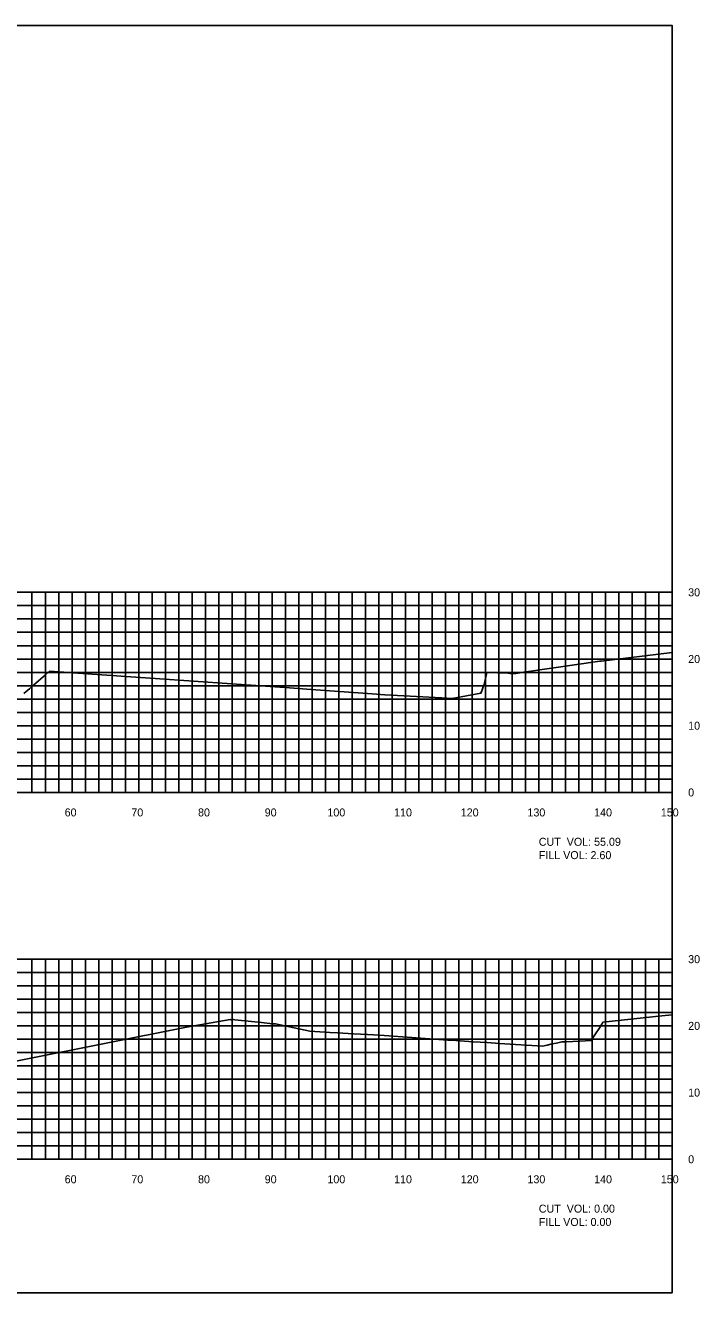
# Model space of a CAD drawing. Extents: x 1800624 to 1802445, y 250079 to 250269.
# Drawn here: x 1802344 to 1802445.1, y 250079.4 to 250269.4 of the extents above; entities that cross this region are included whole.
import ezdxf

# ---------------------------------------------------------------- set-up
doc = ezdxf.new("R2010")
doc.units = 0
for name, color, linetype in [('10', 7, 'Continuous'), ('31', 7, 'Continuous'), ('60', 7, 'Continuous'), ('ANNO-TXT', 7, 'Continuous'), ('Level 62', 7, 'Continuous'), ('M-ROADS', 7, 'Continuous')]:
    doc.layers.add(name, color=color, linetype=linetype)

msp = doc.modelspace()

# ---------------------------------------------------------------- linework, layer by layer
msp.add_lwpolyline([(1802141, 250079.43), (1802441, 250079.43), (1802441, 250269.43), (1802141, 250269.43)], close=True)
at = {"layer": '60'}
for p, q in [((1802441, 250154.43), (1802441, 250184.43)), ((1802441.06, 250184.43), (1802441, 250184.43)), ((1802441.06, 250174.43), (1802441, 250174.43)), ((1802441.06, 250164.43), (1802441, 250164.43)), ((1802141, 250154.43), (1802441, 250154.43)), ((1802351, 250154.37), (1802351, 250154.43)), ((1802361, 250154.37), (1802361, 250154.43)), ((1802371, 250154.37), (1802371, 250154.43)), ((1802381, 250154.37), (1802381, 250154.43)), ((1802391, 250154.37), (1802391, 250154.43)), ((1802401, 250154.37), (1802401, 250154.43)), ((1802411, 250154.37), (1802411, 250154.43)), ((1802421, 250154.37), (1802421, 250154.43)), ((1802431, 250154.37), (1802431, 250154.43)), ((1802441, 250154.37), (1802441, 250154.43)), ((1802441.06, 250154.43), (1802441, 250154.43)), ((1802441, 250099.43), (1802441, 250129.43)), ((1802441.06, 250129.43), (1802441, 250129.43)), ((1802441.06, 250119.43), (1802441, 250119.43)), ((1802441.06, 250109.43), (1802441, 250109.43)), ((1802141, 250099.43), (1802441, 250099.43)), ((1802351, 250099.37), (1802351, 250099.43)), ((1802361, 250099.37), (1802361, 250099.43)), ((1802371, 250099.37), (1802371, 250099.43)), ((1802381, 250099.37), (1802381, 250099.43)), ((1802391, 250099.37), (1802391, 250099.43)), ((1802401, 250099.37), (1802401, 250099.43)), ((1802411, 250099.37), (1802411, 250099.43)), ((1802421, 250099.37), (1802421, 250099.43)), ((1802431, 250099.37), (1802431, 250099.43)), ((1802441, 250099.37), (1802441, 250099.43)), ((1802441.06, 250099.43), (1802441, 250099.43))]:
    msp.add_line(p, q, dxfattribs=at)
at = {"layer": 'Level 62'}
for p, q in [((1802141, 250184.43), (1802441, 250184.43)), ((1802345, 250154.43), (1802345, 250184.43)), ((1802347, 250154.43), (1802347, 250184.43)), ((1802349, 250154.43), (1802349, 250184.43)), ((1802351, 250154.43), (1802351, 250184.43)), ((1802353, 250154.43), (1802353, 250184.43)), ((1802355, 250154.43), (1802355, 250184.43)), ((1802357, 250154.43), (1802357, 250184.43)), ((1802359, 250154.43), (1802359, 250184.43)), ((1802361, 250154.43), (1802361, 250184.43)), ((1802363, 250154.43), (1802363, 250184.43)), ((1802365, 250154.43), (1802365, 250184.43)), ((1802367, 250154.43), (1802367, 250184.43)), ((1802369, 250154.43), (1802369, 250184.43)), ((1802371, 250154.43), (1802371, 250184.43)), ((1802373, 250154.43), (1802373, 250184.43)), ((1802375, 250154.43), (1802375, 250184.43)), ((1802377, 250154.43), (1802377, 250184.43)), ((1802379, 250154.43), (1802379, 250184.43)), ((1802381, 250154.43), (1802381, 250184.43)), ((1802383, 250154.43), (1802383, 250184.43)), ((1802385, 250154.43), (1802385, 250184.43)), ((1802387, 250154.43), (1802387, 250184.43)), ((1802389, 250154.43), (1802389, 250184.43)), ((1802391, 250154.43), (1802391, 250184.43)), ((1802393, 250154.43), (1802393, 250184.43)), ((1802395, 250154.43), (1802395, 250184.43)), ((1802397, 250154.43), (1802397, 250184.43)), ((1802399, 250154.43), (1802399, 250184.43)), ((1802401, 250154.43), (1802401, 250184.43)), ((1802403, 250154.43), (1802403, 250184.43)), ((1802405, 250154.43), (1802405, 250184.43)), ((1802407, 250154.43), (1802407, 250184.43)), ((1802409, 250154.43), (1802409, 250184.43)), ((1802411, 250154.43), (1802411, 250184.43)), ((1802413, 250154.43), (1802413, 250184.43)), ((1802415, 250154.43), (1802415, 250184.43)), ((1802417, 250154.43), (1802417, 250184.43)), ((1802419, 250154.43), (1802419, 250184.43)), ((1802421, 250154.43), (1802421, 250184.43)), ((1802423, 250154.43), (1802423, 250184.43)), ((1802425, 250154.43), (1802425, 250184.43)), ((1802427, 250154.43), (1802427, 250184.43)), ((1802429, 250154.43), (1802429, 250184.43)), ((1802431, 250154.43), (1802431, 250184.43)), ((1802433, 250154.43), (1802433, 250184.43)), ((1802435, 250154.43), (1802435, 250184.43)), ((1802437, 250154.43), (1802437, 250184.43)), ((1802439, 250154.43), (1802439, 250184.43)), ((1802441, 250154.43), (1802441, 250184.43)), ((1802141, 250182.43), (1802441, 250182.43)), ((1802141, 250180.43), (1802441, 250180.43)), ((1802141, 250178.43), (1802441, 250178.43)), ((1802141, 250176.43), (1802441, 250176.43)), ((1802141, 250174.43), (1802441, 250174.43)), ((1802141, 250172.43), (1802441, 250172.43)), ((1802141, 250170.43), (1802441, 250170.43)), ((1802141, 250168.43), (1802441, 250168.43)), ((1802141, 250166.43), (1802441, 250166.43)), ((1802141, 250164.43), (1802441, 250164.43)), ((1802141, 250162.43), (1802441, 250162.43)), ((1802141, 250160.43), (1802441, 250160.43)), ((1802141, 250158.43), (1802441, 250158.43)), ((1802141, 250156.43), (1802441, 250156.43)), ((1802141, 250154.43), (1802441, 250154.43)), ((1802141, 250129.43), (1802441, 250129.43)), ((1802345, 250099.43), (1802345, 250129.43)), ((1802347, 250099.43), (1802347, 250129.43)), ((1802349, 250099.43), (1802349, 250129.43)), ((1802351, 250099.43), (1802351, 250129.43)), ((1802353, 250099.43), (1802353, 250129.43)), ((1802355, 250099.43), (1802355, 250129.43)), ((1802357, 250099.43), (1802357, 250129.43)), ((1802359, 250099.43), (1802359, 250129.43)), ((1802361, 250099.43), (1802361, 250129.43)), ((1802363, 250099.43), (1802363, 250129.43)), ((1802365, 250099.43), (1802365, 250129.43)), ((1802367, 250099.43), (1802367, 250129.43)), ((1802369, 250099.43), (1802369, 250129.43)), ((1802371, 250099.43), (1802371, 250129.43)), ((1802373, 250099.43), (1802373, 250129.43)), ((1802375, 250099.43), (1802375, 250129.43)), ((1802377, 250099.43), (1802377, 250129.43)), ((1802379, 250099.43), (1802379, 250129.43)), ((1802381, 250099.43), (1802381, 250129.43)), ((1802383, 250099.43), (1802383, 250129.43)), ((1802385, 250099.43), (1802385, 250129.43)), ((1802387, 250099.43), (1802387, 250129.43)), ((1802389, 250099.43), (1802389, 250129.43)), ((1802391, 250099.43), (1802391, 250129.43)), ((1802393, 250099.43), (1802393, 250129.43)), ((1802395, 250099.43), (1802395, 250129.43)), ((1802397, 250099.43), (1802397, 250129.43)), ((1802399, 250099.43), (1802399, 250129.43)), ((1802401, 250099.43), (1802401, 250129.43)), ((1802403, 250099.43), (1802403, 250129.43)), ((1802405, 250099.43), (1802405, 250129.43)), ((1802407, 250099.43), (1802407, 250129.43)), ((1802409, 250099.43), (1802409, 250129.43)), ((1802411, 250099.43), (1802411, 250129.43)), ((1802413, 250099.43), (1802413, 250129.43)), ((1802415, 250099.43), (1802415, 250129.43)), ((1802417, 250099.43), (1802417, 250129.43)), ((1802419, 250099.43), (1802419, 250129.43)), ((1802421, 250099.43), (1802421, 250129.43)), ((1802423, 250099.43), (1802423, 250129.43)), ((1802425, 250099.43), (1802425, 250129.43)), ((1802427, 250099.43), (1802427, 250129.43)), ((1802429, 250099.43), (1802429, 250129.43)), ((1802431, 250099.43), (1802431, 250129.43)), ((1802433, 250099.43), (1802433, 250129.43)), ((1802435, 250099.43), (1802435, 250129.43)), ((1802437, 250099.43), (1802437, 250129.43)), ((1802439, 250099.43), (1802439, 250129.43)), ((1802441, 250099.43), (1802441, 250129.43)), ((1802141, 250127.43), (1802441, 250127.43)), ((1802141, 250125.43), (1802441, 250125.43)), ((1802141, 250123.43), (1802441, 250123.43)), ((1802141, 250121.43), (1802441, 250121.43)), ((1802141, 250119.43), (1802441, 250119.43)), ((1802141, 250117.43), (1802441, 250117.43)), ((1802141, 250115.43), (1802441, 250115.43)), ((1802141, 250113.43), (1802441, 250113.43)), ((1802141, 250111.43), (1802441, 250111.43)), ((1802141, 250109.43), (1802441, 250109.43)), ((1802141, 250107.43), (1802441, 250107.43)), ((1802141, 250105.43), (1802441, 250105.43)), ((1802141, 250103.43), (1802441, 250103.43)), ((1802141, 250101.43), (1802441, 250101.43)), ((1802141, 250099.43), (1802441, 250099.43))]:
    msp.add_line(p, q, dxfattribs=at)
at = {"layer": 'M-ROADS'}
for points in [[(1802343.77, 250169.24), (1802344.15, 250169.57), (1802344.62, 250169.98), (1802345.21, 250170.5), (1802345.98, 250171.17), (1802347.03, 250172.08), (1802347.62, 250172.59), (1802354.04, 250172.16), (1802363.49, 250171.52), (1802374.98, 250170.71), (1802383.62, 250170.11), (1802386.84, 250169.87), (1802396, 250169.19), (1802397.93, 250169.08), (1802402.64, 250168.83), (1802406.42, 250168.62), (1802407.99, 250168.53), (1802409.36, 250168.77), (1802412.32, 250169.29), (1802412.44, 250169.65), (1802412.66, 250170.25), (1802412.79, 250170.63), (1802413.19, 250172.41), (1802416.43, 250172.3), (1802416.72, 250172.28), (1802416.98, 250172.27), (1802417.04, 250172.25), (1802417.11, 250172.25), (1802417.54, 250172.26), (1802419.01, 250172.5), (1802419.13, 250172.51), (1802430.17, 250174.11), (1802430.33, 250174.11), (1802441, 250175.4)], [(1802331.71, 250112.01), (1802368.18, 250119.22), (1802374.72, 250120.37), (1802374.86, 250120.34), (1802375.09, 250120.37), (1802375.23, 250120.38), (1802375.43, 250120.34), (1802378.41, 250120.03), (1802379.44, 250119.91), (1802381.07, 250119.71), (1802381.09, 250119.71), (1802381.54, 250119.73), (1802383.64, 250119.27), (1802386.67, 250118.63), (1802389.66, 250118.45), (1802390.8, 250118.39), (1802393.21, 250118.25), (1802395.33, 250118.13), (1802397.11, 250118.03), (1802401.28, 250117.73), (1802405.99, 250117.4), (1802407.37, 250117.3), (1802408.58, 250117.22), (1802411.16, 250117.05), (1802413.26, 250116.92), (1802415.12, 250116.81), (1802421.54, 250116.4), (1802422.24, 250116.55), (1802422.79, 250116.69), (1802423.87, 250116.89), (1802424.47, 250117.02), (1802424.64, 250117.06), (1802424.66, 250117.06), (1802425.13, 250117.06), (1802426.1, 250117.1), (1802427.17, 250117.15), (1802428.87, 250117.22), (1802429.52, 250118.23), (1802430.04, 250119.04), (1802430.29, 250119.44), (1802430.37, 250119.55), (1802430.43, 250119.66), (1802430.61, 250119.97), (1802439.44, 250120.93), (1802441, 250121.1)]]:
    msp.add_lwpolyline(points, dxfattribs=at)

# ---------------------------------------------------------------- texts
at = {"layer": '10'}
for s, p in [('60', (1802349.9, 250150.83)), ('70', (1802359.9, 250150.83)), ('80', (1802369.9, 250150.83)), ('90', (1802379.9, 250150.83)), ('100', (1802389.3, 250150.83)), ('110', (1802399.3, 250150.83)), ('120', (1802409.3, 250150.83)), ('130', (1802419.3, 250150.83)), ('140', (1802429.3, 250150.83)), ('150', (1802439.3, 250150.83)), ('60', (1802349.9, 250095.83)), ('70', (1802359.9, 250095.83)), ('80', (1802369.9, 250095.83)), ('90', (1802379.9, 250095.83)), ('100', (1802389.3, 250095.83)), ('110', (1802399.3, 250095.83)), ('120', (1802409.3, 250095.83)), ('130', (1802419.3, 250095.83)), ('140', (1802429.3, 250095.83)), ('150', (1802439.3, 250095.83))]:
    msp.add_text(s, height=1.2, dxfattribs=at).set_placement(p)
at = {"layer": '31'}
for s, p in [('30', (1802443.4, 250183.83)), ('20', (1802443.4, 250173.83)), ('10', (1802443.4, 250163.83)), ('0', (1802443.4, 250153.83)), ('30', (1802443.4, 250128.83)), ('20', (1802443.4, 250118.83)), ('10', (1802443.4, 250108.83)), ('0', (1802443.4, 250098.83))]:
    msp.add_text(s, height=1.2, dxfattribs=at).set_placement(p)
at = {"layer": 'ANNO-TXT'}
for s, p in [('CUT  VOL: 55.09', (1802421, 250146.43)), ('FILL VOL: 2.60', (1802421, 250144.43)), ('CUT  VOL: 0.00', (1802421, 250091.43)), ('FILL VOL: 0.00', (1802421, 250089.43))]:
    msp.add_text(s, height=1.2, dxfattribs=at).set_placement(p)

doc.saveas('drawing.dxf')
